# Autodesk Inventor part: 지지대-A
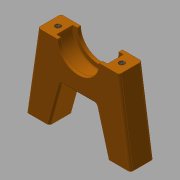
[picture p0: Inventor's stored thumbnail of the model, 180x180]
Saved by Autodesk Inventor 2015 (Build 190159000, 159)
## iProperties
Created: 2018-01
Part Number: 지지대-A
Material: 알루미늄 6061
Document SubType Name: Modeling
Designer: mduedu
Density: 2.71 g/cm^3
Appearance: 주황색
Author: mduedu
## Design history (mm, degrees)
sketch "스케치1"
  geometry: L1 (-22.5, 0)-(22.5, 0); L2 (22.5, 0)-(17.5, 34); L3 (17.5, 34)-(-17.5, 34); L4 (-17.5, 34)-(-22.5, 0); 3 further points
  constraints: 8 end point, 2 midpoint, 1 coincident, 1 horizontal, 1 parallel, 1 vertical alignment
  dimensions: "d0" = 45 distance of L1.start L1.end; "d3" = 35 distance of L2.end L3.end; "d4" = 34 vertical distance of L1.end L2.end
extrude "돌출1" new body sketch "스케치1" stored distance "d5" = 10; taper "d6" = 0 deg
sketch "스케치2"
  geometry: L1 (-12.5, 0)-(12.5, 0); L2 (12.5, 0)-(7.5, 18); L3 (7.5, 18)-(-7.5, 18); L4 (-7.5, 18)-(-12.5, 0); L5 (-22.5, 0)-(22.5, 0) reference; 4 further points
  constraints: 8 end point, 4 midpoint, 1 horizontal, 1 parallel, 1 vertical alignment
  dimensions: "d7" = 10 distance of L1.start L5.start; "d8" = 10 distance of L1.end L5.end (derived); "d9" = 15 distance of L2.end L3.end; "d10" = 18 distance between parallel lines of L1 L3
extrude "돌출2" cut sketch "스케치2" stored distance "d11" = 10; taper "d12" = 0 deg
sketch "스케치3"
  geometry: L1 (-17.5, 34)-(17.5, 34) reference; C1 r 11 at (0, 34); C2 r 9 at (0, 34); 1 further point
  constraints: 2 centre point, 1 coincident, 1 midpoint
  dimensions: "d13" = 22 diameter of C1; "d16" = 18 diameter of C2
extrude "돌출3" cut sketch "스케치3" stored distance "d14" = 7; taper "d15" = 0 deg
extrude "돌출4" cut sketch "스케치3" stored distance "d17" = 7; taper "d18" = 0 deg
fillet "모깎기1" dims "d19" = 0.3
fillet "모깎기2" dims "d20" = 1
fillet "모깎기3" dims "d21" = 1
fillet "모깎기4" dims "d22" = 1
sketch "스케치4"
  geometry: 2 further points
  constraints: 2 other
hole "구멍1" sketch "스케치4" at (-22.771, -3.5), (4.771, -3.5) diameter "d23" = 2.459; stored, may be unused: countersink angle "d27" = 90 deg, drill point angle "d29" = 120 deg; dims "d24" = 4.5, "d25" = 4, "d26" = 2, "d28" = 6
sketch "스케치5"
  geometry: 4 further points
  constraints: 4 other
hole "구멍2" sketch "스케치5" at (40, 4), (5, -27), (40, -27), (5, 4) diameter "d30" = 2.459; stored, may be unused: countersink angle "d34" = 90 deg, drill point angle "d36" = 120 deg; dims "d31" = 6.9, "d32" = 4, "d33" = 2, "d35" = 8.4
node "솔리드1"
